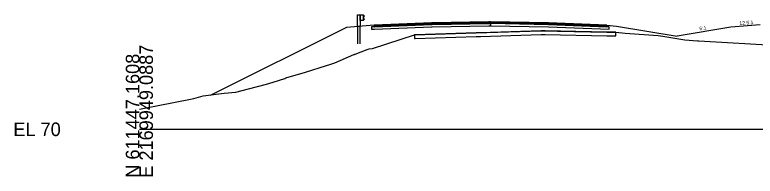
# Model space of a CAD drawing. Extents: x -26 to 1303, y -3010 to 12023.
# Drawn here: x 974.3 to 1127, y 3990.3 to 4023.7 of the extents above; entities that cross this region are included whole.
import ezdxf

# ---------------------------------------------------------------- set-up
doc = ezdxf.new("R2010")
doc.units = 0
for name, color, linetype in [('RD_GPK_XS_Cell', 7, 'Continuous'), ('RD_PD_Final_TrvlWay', 7, 'Continuous'), ('RD_XS_Base', 7, 'Continuous'), ('RD_XS_ExGround', 7, 'Continuous'), ('RD_XS_ExPaveRet', 7, 'Continuous'), ('RD_XS_GR', 7, 'Continuous'), ('RD_XS_Greenside', 7, 'Continuous'), ('RD_XS_Pave', 7, 'Continuous'), ('RD_XS_PaveOvlay_CP', 7, 'Continuous'), ('RD_XS_TieSlope', 7, 'Continuous'), ('RD_XS_TX_ShdSlope', 7, 'Continuous'), ('RD_XS_TX_Slope', 7, 'Continuous')]:
    doc.layers.add(name, color=color, linetype=linetype)

msp = doc.modelspace()

# ---------------------------------------------------------------- linework, layer by layer
at = {"layer": 'RD_GPK_XS_Cell'}
msp.add_line((1000, 4000), (1150, 4000), dxfattribs=at)
at = {"layer": 'RD_PD_Final_TrvlWay'}
msp.add_lwpolyline([(1045.5, 4017.66), (1045.5, 4021.26), (1045, 4021.22), (1045, 4017.66)], dxfattribs=at)
at = {"layer": 'RD_XS_Base'}
for p, q in [((1072.39, 4021.9), (1072.39, 4022.05)), ((1072.39, 4022.05), (1072.39, 4022.05)), ((1072.39, 4022.05), (1072.39, 4022.04)), ((1072.39, 4021.9), (1072.39, 4022.05)), ((1072.39, 4022.05), (1072.39, 4022.05)), ((1072.39, 4022.05), (1072.39, 4022.05)), ((1072.39, 4022.05), (1072.39, 4021.4)), ((1072.39, 4022.04), (1072.39, 4021.4)), ((1048.39, 4021.18), (1047.89, 4021.16)), ((1047.89, 4021.16), (1047.89, 4021.16)), ((1047.89, 4021.16), (1047.89, 4020.66)), ((1047.89, 4020.66), (1048.39, 4020.68)), ((1047.89, 4020.66), (1047.89, 4020.66)), ((1047.89, 4020.66), (1047.89, 4020.66)), ((1048.39, 4021.18), (1048.39, 4021.18)), ((1048.48, 4021.18), (1048.39, 4021.18)), ((1048.39, 4020.68), (1048.39, 4020.68)), ((1048.39, 4020.68), (1048.48, 4020.68)), ((1060.24, 4021.65), (1048.48, 4021.18)), ((1048.48, 4020.68), (1060.24, 4021.15)), ((1060.39, 4021.66), (1060.24, 4021.65)), ((1060.24, 4021.15), (1060.39, 4021.16)), ((1072.08, 4021.89), (1060.39, 4021.66)), ((1060.39, 4021.16), (1072.08, 4021.39)), ((1072.39, 4021.9), (1072.08, 4021.89)), ((1072.08, 4021.39), (1072.39, 4021.4)), ((1072.39, 4021.88), (1072.39, 4021.9)), ((1072.39, 4021.4), (1072.39, 4021.9)), ((1072.39, 4021.9), (1072.39, 4021.9)), ((1072.39, 4021.9), (1072.39, 4021.9)), ((1072.39, 4021.9), (1072.39, 4021.9)), ((1084.39, 4021.66), (1072.39, 4021.9)), ((1072.39, 4021.4), (1072.39, 4021.88)), ((1072.39, 4021.4), (1072.39, 4021.4)), ((1072.39, 4021.4), (1072.39, 4021.4)), ((1072.39, 4021.4), (1084.39, 4021.16)), ((1096.39, 4021.18), (1084.39, 4021.66)), ((1084.39, 4021.16), (1096.89, 4020.66)), ((1086.39, 4021.58), (1086.39, 4021.58)), ((1086.39, 4021.08), (1086.39, 4021.08)), ((1096.89, 4021.16), (1096.39, 4021.18)), ((1096.39, 4021.18), (1096.39, 4021.18)), ((1096.89, 4020.66), (1096.89, 4021.16)), ((1096.89, 4021.16), (1096.89, 4021.16))]:
    msp.add_line(p, q, dxfattribs=at)
at = {"layer": 'RD_XS_ExGround'}
msp.add_lwpolyline([(1000, 4004.14), (1010.88, 4006.29), (1011.23, 4006.36), (1013.12, 4006.89), (1017.46, 4007.48), (1019.9, 4007.68), (1022.47, 4008.39), (1026.2, 4009.31), (1027.58, 4009.76), (1030.01, 4010.5), (1030.18, 4010.61), (1034.26, 4011.81), (1038.61, 4013.18), (1039.25, 4013.37), (1040.28, 4013.75), (1044.21, 4015.42), (1044.35, 4015.48), (1044.4, 4015.5), (1044.5, 4015.54), (1046.99, 4016.51), (1047.4, 4016.62), (1048.09, 4016.71), (1056.71, 4019.49), (1069.46, 4019.9), (1082.88, 4020.33), (1096.4, 4020.09), (1098.25, 4020.05), (1100.22, 4019.84), (1106.98, 4019.37), (1107.93, 4019.22), (1112.48, 4018.5), (1115.13, 4018.29), (1115.38, 4018.27), (1131.96, 4017.31)], dxfattribs=at)
at = {"layer": 'RD_XS_ExPaveRet'}
msp.add_lwpolyline([(1096.4, 4020.09), (1083.7, 4020.31), (1082.88, 4020.33), (1070.38, 4019.93), (1069.46, 4019.9), (1056.85, 4019.5), (1056.71, 4019.49), (1056.71, 4018.76), (1056.71, 4018.74), (1056.85, 4018.75), (1069.46, 4019.15), (1070.38, 4019.18), (1082.88, 4019.58), (1083.7, 4019.56), (1096.4, 4019.34), (1096.94, 4019.33), (1098.25, 4019.3), (1098.25, 4019.97), (1098.25, 4020.05), (1096.94, 4020.08), (1096.4, 4020.09)], dxfattribs=at)
msp.add_lwpolyline([(1096.4, 4020.09), (1083.7, 4020.31), (1082.88, 4020.33), (1070.38, 4019.93), (1069.46, 4019.9), (1056.85, 4019.5), (1056.71, 4019.49), (1056.71, 4018.76), (1056.71, 4018.74), (1056.85, 4018.75), (1069.46, 4019.15), (1070.38, 4019.18), (1082.88, 4019.58), (1083.7, 4019.56), (1096.4, 4019.34), (1096.94, 4019.33), (1098.25, 4019.3), (1098.25, 4019.97), (1098.25, 4020.05), (1096.94, 4020.08), (1096.4, 4020.09)], dxfattribs=at)
at = {"layer": 'RD_XS_GR'}
for p, q in [((1045, 4021.22), (1045, 4023.66)), ((1045, 4023.66), (1045.25, 4023.66)), ((1045.25, 4023.66), (1045.5, 4023.66)), ((1045.5, 4023.66), (1045.5, 4021.26)), ((1045.5, 4022.49), (1045.5, 4023.66)), ((1045.5, 4023.66), (1046.17, 4023.66)), ((1046.17, 4023.66), (1046.17, 4022.49)), ((1046.44, 4023.37), (1046.17, 4023.66)), ((1046.17, 4023.66), (1046.17, 4022.49)), ((1046.17, 4022.49), (1045.5, 4022.49)), ((1046.17, 4023.08), (1046.44, 4023.37)), ((1046.17, 4023.07), (1046.17, 4023.08)), ((1046.44, 4022.78), (1046.17, 4023.07)), ((1046.17, 4022.49), (1046.44, 4022.78)), ((1046.17, 4022.49), (1046.17, 4022.49)), ((1046.17, 4022.49), (1046.17, 4022.49)), ((1046.44, 4023.37), (1046.44, 4023.37)), ((1046.44, 4022.78), (1046.44, 4022.78)), ((1045.5, 4021.26), (1045, 4021.22))]:
    msp.add_line(p, q, dxfattribs=at)
at = {"layer": 'RD_XS_Greenside'}
for p, q in [((1042.69, 4021.04), (1014.63, 4007.01)), ((1098.39, 4021.33), (1110.92, 4019.25)), ((1122, 4021.09), (1110.92, 4019.25))]:
    msp.add_line(p, q, dxfattribs=at)
at = {"layer": 'RD_XS_Pave'}
for p, q in [((1072.08, 4022.21), (1060.39, 4021.97)), ((1072.08, 4022.05), (1060.39, 4021.81)), ((1060.39, 4021.81), (1072.08, 4022.05)), ((1072.39, 4022.21), (1072.08, 4022.21)), ((1072.39, 4022.05), (1072.08, 4022.05)), ((1072.08, 4022.05), (1072.39, 4022.05)), ((1084.39, 4021.97), (1072.39, 4022.21)), ((1072.39, 4022.21), (1072.39, 4022.21)), ((1072.39, 4022.21), (1072.39, 4022.21)), ((1072.39, 4021.9), (1072.39, 4022.05)), ((1072.39, 4022.05), (1072.39, 4022.05)), ((1072.39, 4022.05), (1072.39, 4022.05)), ((1072.39, 4022.05), (1072.39, 4021.9)), ((1072.39, 4021.9), (1072.39, 4022.05)), ((1072.39, 4022.05), (1072.39, 4022.05)), ((1072.39, 4022.05), (1072.39, 4022.05)), ((1072.39, 4022.05), (1072.39, 4022.05)), ((1072.39, 4022.05), (1072.39, 4022.05)), ((1072.39, 4022.05), (1084.39, 4021.81)), ((1084.39, 4021.81), (1072.39, 4022.05)), ((1072.39, 4022.05), (1072.39, 4022.05)), ((1072.39, 4022.05), (1072.39, 4022.05)), ((1072.39, 4022.05), (1072.39, 4021.9)), ((1048.48, 4021.5), (1048.39, 4021.49)), ((1048.39, 4021.49), (1048.39, 4021.49)), ((1048.39, 4021.49), (1048.39, 4021.33)), ((1048.48, 4021.34), (1048.39, 4021.33)), ((1048.39, 4021.33), (1048.48, 4021.34)), ((1048.39, 4021.33), (1048.39, 4021.33)), ((1048.39, 4021.33), (1048.39, 4021.18)), ((1048.39, 4021.33), (1048.39, 4021.33)), ((1048.39, 4021.33), (1048.39, 4021.33)), ((1048.39, 4021.18), (1048.39, 4021.18)), ((1048.39, 4021.18), (1048.39, 4021.18)), ((1048.39, 4021.18), (1048.48, 4021.18)), ((1060.24, 4021.97), (1048.48, 4021.5)), ((1060.24, 4021.81), (1048.48, 4021.34)), ((1048.48, 4021.34), (1060.24, 4021.81)), ((1048.48, 4021.18), (1060.24, 4021.65)), ((1060.39, 4021.97), (1060.24, 4021.97)), ((1060.39, 4021.81), (1060.24, 4021.81)), ((1060.24, 4021.81), (1060.39, 4021.81)), ((1060.24, 4021.65), (1060.39, 4021.66)), ((1060.39, 4021.66), (1072.08, 4021.89)), ((1072.08, 4021.89), (1072.39, 4021.9)), ((1072.39, 4021.9), (1072.39, 4021.9)), ((1072.39, 4021.9), (1072.39, 4021.9)), ((1072.39, 4021.9), (1084.39, 4021.66)), ((1096.39, 4021.49), (1084.39, 4021.97)), ((1084.39, 4021.81), (1096.39, 4021.33)), ((1096.39, 4021.33), (1084.39, 4021.81)), ((1084.39, 4021.66), (1096.39, 4021.18)), ((1086.39, 4021.89), (1086.39, 4021.89)), ((1086.39, 4021.73), (1086.39, 4021.73)), ((1086.39, 4021.73), (1086.39, 4021.73)), ((1086.39, 4021.58), (1086.39, 4021.58)), ((1096.39, 4021.33), (1096.39, 4021.49)), ((1096.39, 4021.49), (1096.39, 4021.49)), ((1096.39, 4021.18), (1096.39, 4021.33)), ((1096.39, 4021.33), (1096.39, 4021.33))]:
    msp.add_line(p, q, dxfattribs=at)
at = {"layer": 'RD_XS_PaveOvlay_CP'}
for p, q in [((1060.39, 4021.97), (1072.39, 4022.21)), ((1072.39, 4022.21), (1084.39, 4021.97)), ((1048.39, 4021.49), (1048.48, 4021.5)), ((1048.48, 4021.5), (1060.39, 4021.97)), ((1084.39, 4021.97), (1096.39, 4021.49))]:
    msp.add_line(p, q, dxfattribs=at)
at = {"layer": 'RD_XS_TieSlope'}
for p, q in [((1048.39, 4021.49), (1042.69, 4021.04)), ((1096.39, 4021.49), (1098.39, 4021.33)), ((1128, 4021.57), (1122, 4021.09))]:
    msp.add_line(p, q, dxfattribs=at)

# ---------------------------------------------------------------- texts
at = {"layer": 'RD_GPK_XS_Cell'}
for s, p in [('E 2169949.0887', (1002.8, 3990)), ('N 611447.1608', (1000, 3990))]:
    msp.add_text(s, height=2.8, rotation=90, dxfattribs=at).set_placement(p)
msp.add_text('EL 70', height=2.8, dxfattribs=at).set_placement((974, 3998.6))
at = {"layer": 'RD_XS_TX_ShdSlope'}
msp.add_text('12.5:1', height=0.75, rotation=4.5739, dxfattribs=at).set_placement((1123.78, 4021.52))
at = {"layer": 'RD_XS_TX_Slope'}
msp.add_text('6:1', height=0.75, rotation=9.4642, dxfattribs=at).set_placement((1115.57, 4020.43))

doc.saveas('drawing.dxf')
